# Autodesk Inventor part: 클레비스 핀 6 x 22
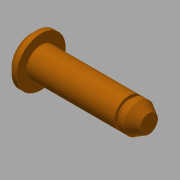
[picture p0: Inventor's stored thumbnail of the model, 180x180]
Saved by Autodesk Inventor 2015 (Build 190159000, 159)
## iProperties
IsCustomPart: 1
Created: 2017-08
Part Number: 클레비스 핀 6 x 22
Material: 강철
Description: 머리가 있는 클레비스 핀
Document SubType Name: Modeling
Standard: ISO 2341
Designer: mduedu
Standard Revision: Second edition 1986-11-01
Standards Organization: ISO
Language: ko-KR
Size Designation: B - 6 x 24
Categories: <MemberInstance><Categories><Category DisplayName="조임쇠" InternalName="e4da775c-781d-43d5-af7c-5136215cf5a6" Mnemonic="FSTN"><Category DisplayName="핀" InternalNa
Density: 7.85 g/cm^3
Appearance: 주황색
Author: mduedu
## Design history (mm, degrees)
sketch "스케치1"
  geometry: L1 (-2, 0)-(-2, 5); L2 (-2, 5)-(0, 5); L3 (0, 5)-(0, 3); L4 (0, 3)-(22, 3); L5 (22, 3)-(22, 0); L6 (-2, 0)-(22, 0); L7 (-7, 0)-(28, 0) reference; L8 (0, -1.96)-(0, 6.16) reference; C1 r 0.8 at (18.8, 0)
  constraints: 12 end point, 3 parallel, 2 collinear, 2 perpendicular, 1 centre point, 1 point on line, 1 vertical
  dimensions: "d0" = 6 diameter of L4 L6 (= NND); "d1" = 10 diameter of L2 L6 (= KOD); "d2" = 2 distance of L1.end L2.end (= KOH); "d3" = 22 distance of L3.end L4.end (= NLG); "d5" = 3.2 distance from line of L5 C1.centre (= DIST); "d6" = 1.6 diameter of C1 (= BOR)
revolve "본체" stored, may be unused: angle "d4" = 90 deg
workplane "Work Plane1"
node "작업 평면4"
sketch "스케치2"
  geometry: C1 r 3 at (0, 0) reference; C2 r 2.425 at (0, 0); 1 further point
  constraints: 1 centre point, 1 coincident
  dimensions: "d33" = 4.85 diameter of C2
extrude "돌출2" cut sketch "스케치2" distance "d34" = 0.7; taper "d35" = 0 deg
body "Solid1"
chamfer "모따기1" distance "d9" = 1 (= PHH2); stored, may be unused: angle "d10" = 45 deg (= FAWI2), second distance "d16" = 1 (= PHH2)
chamfer "모따기2" distance "d11" = 2 (= PHH1); stored, may be unused: angle "d12" = 30 deg (= FAWI1), second distance "d17" = 2 (= PHH1)
other parameters: "PHH1" = 2 [user parameter; used in 2 equation terms], "PHH2" = 1 [user parameter; used in 2 equation terms], "KOD" = 10 [user parameter; used in 1 equation term], "KOH" = 2 [user parameter; used in 1 equation term], "NND" = 6 [user parameter; used in 1 equation term], "FAWI1" = 30 deg [user parameter; used in 1 equation term], "FAWI2" = 45 deg [user parameter; used in 1 equation term], "DIST" = 3.2 [user parameter; used in 1 equation term], "BOR" = 1.6 [user parameter; used in 1 equation term], "NLG" = 22 [user parameter; used in 1 equation term], "d13" = 0, "d14" = 0, "d30" = 0, "d32" = 18
